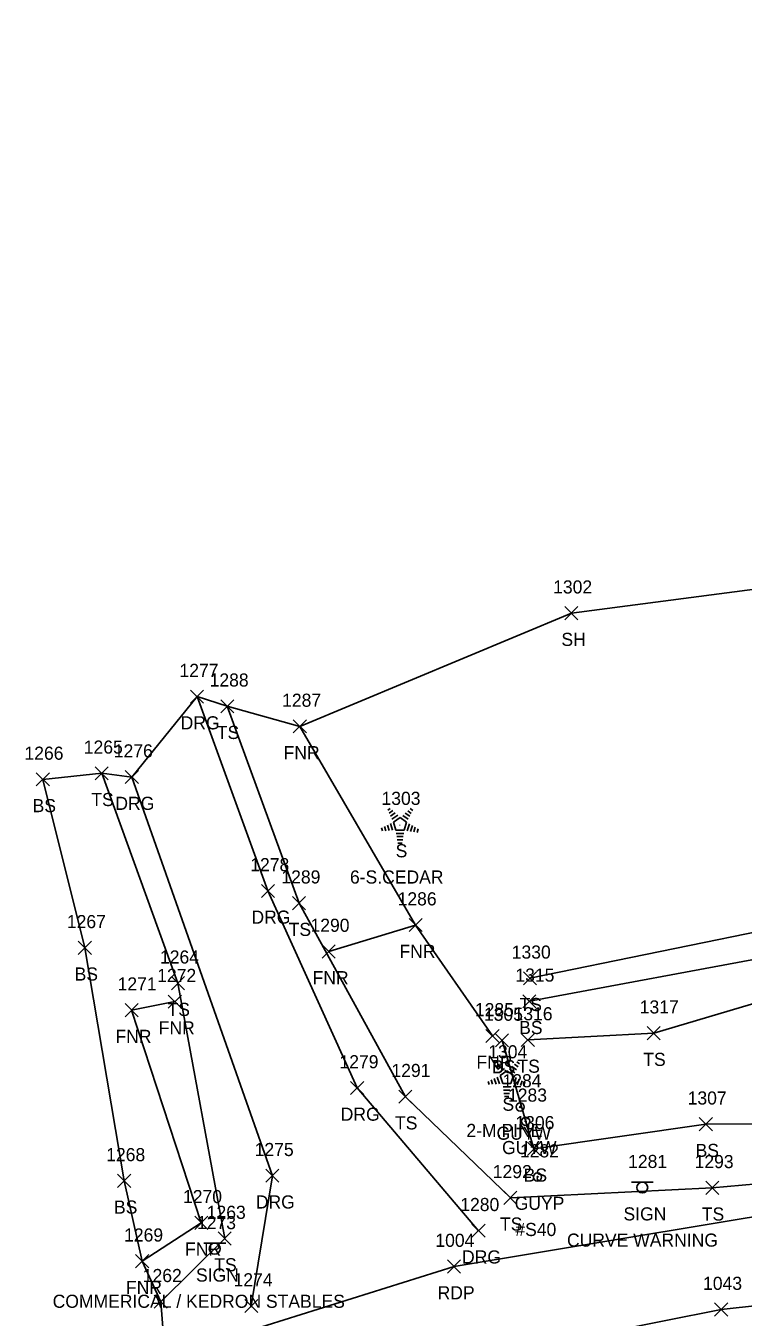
# Model space of a CAD drawing. Extents: x 1633660 to 1636532, y 388643 to 392631.
# Drawn here: x 1633659.9 to 1633769.3, y 388760.6 to 388957.6 of the extents above; entities that cross this region are included whole.
import ezdxf

# ---------------------------------------------------------------- set-up
doc = ezdxf.new("R2010")
doc.units = 0
for name, color, linetype in [('L_A', 7, 'Continuous'), ('L_C', 7, 'Continuous'), ('L_I', 7, 'Continuous'), ('L_TIC', 7, 'Continuous'), ('LELB', 7, 'Continuous'), ('LFNC', 7, 'Continuous'), ('LSOGP', 7, 'Continuous'), ('LTC', 7, 'Continuous'), ('P_A', 7, 'Continuous'), ('P_I', 7, 'Continuous'), ('P_TIC', 7, 'Continuous'), ('PET', 7, 'Continuous'), ('PRC', 7, 'Continuous'), ('R_A', 7, 'Continuous'), ('R_I', 7, 'Continuous'), ('R_TIC', 7, 'Continuous'), ('RDG', 7, 'Continuous'), ('S_A', 7, 'Continuous'), ('S_C', 7, 'Continuous'), ('S_I', 7, 'Continuous'), ('SSGN', 7, 'Continuous'), ('U_A', 7, 'Continuous'), ('U_C', 7, 'Continuous'), ('U_I', 7, 'Continuous'), ('UPGW', 7, 'Continuous')]:
    doc.layers.add(name, color=color, linetype=linetype)

msp = doc.modelspace()

# ---------------------------------------------------------------- linework, layer by layer
at = {"layer": 'L_TIC'}
for points in [[(1633742.09, 388866.97), (1633744.09, 388868.97)], [(1633744.09, 388866.97), (1633742.09, 388868.97)], [(1633689.59, 388852.77), (1633691.59, 388854.77)], [(1633691.59, 388852.77), (1633689.59, 388854.77)], [(1633700.66, 388849.69), (1633702.66, 388851.69)], [(1633702.66, 388849.69), (1633700.66, 388851.69)], [(1633661.45, 388841.61), (1633663.45, 388843.61)], [(1633663.45, 388841.61), (1633661.45, 388843.61)], [(1633670.44, 388842.54), (1633672.44, 388844.54)], [(1633672.44, 388842.54), (1633670.44, 388844.54)], [(1633700.55, 388822.73), (1633702.55, 388824.73)], [(1633702.55, 388822.73), (1633700.55, 388824.73)], [(1633718.32, 388819.39), (1633720.32, 388821.39)], [(1633720.32, 388819.39), (1633718.32, 388821.39)], [(1633667.86, 388815.92), (1633669.86, 388817.92)], [(1633669.86, 388815.92), (1633667.86, 388817.92)], [(1633705.07, 388815.36), (1633707.07, 388817.36)], [(1633707.07, 388815.36), (1633705.07, 388817.36)], [(1633735.77, 388811.27), (1633737.77, 388813.27)], [(1633737.77, 388811.27), (1633735.77, 388813.27)], [(1633682.07, 388810.52), (1633684.07, 388812.52)], [(1633684.07, 388810.52), (1633682.07, 388812.52)], [(1633681.59, 388807.71), (1633683.59, 388809.71)], [(1633683.59, 388807.71), (1633681.59, 388809.71)], [(1633735.68, 388807.76), (1633737.68, 388809.76)], [(1633737.68, 388807.76), (1633735.68, 388809.76)], [(1633674.99, 388806.41), (1633676.99, 388808.41)], [(1633676.99, 388806.41), (1633674.99, 388808.41)], [(1633730.06, 388802.48), (1633732.06, 388804.48)], [(1633732.06, 388802.48), (1633730.06, 388804.48)], [(1633731.52, 388801.79), (1633733.52, 388803.79)], [(1633733.52, 388801.79), (1633731.52, 388803.79)], [(1633735.45, 388801.86), (1633737.45, 388803.86)], [(1633737.45, 388801.86), (1633735.45, 388803.86)], [(1633754.65, 388802.9), (1633756.65, 388804.9)], [(1633756.65, 388802.9), (1633754.65, 388804.9)], [(1633716.77, 388793.21), (1633718.77, 388795.21)], [(1633718.77, 388793.21), (1633716.77, 388795.21)], [(1633762.6, 388789.01), (1633764.6, 388791.01)], [(1633764.6, 388789.01), (1633762.6, 388791.01)], [(1633736.38, 388785.25), (1633738.38, 388787.25)], [(1633738.38, 388785.25), (1633736.38, 388787.25)], [(1633673.86, 388780.37), (1633675.86, 388782.37)], [(1633675.86, 388780.37), (1633673.86, 388782.37)], [(1633732.79, 388777.78), (1633734.79, 388779.78)], [(1633734.79, 388777.78), (1633732.79, 388779.78)], [(1633763.59, 388779.31), (1633765.59, 388781.31)], [(1633765.59, 388779.31), (1633763.59, 388781.31)], [(1633685.62, 388773.97), (1633687.62, 388775.97)], [(1633687.62, 388773.97), (1633685.62, 388775.97)], [(1633689.2, 388771.57), (1633691.2, 388773.57)], [(1633691.2, 388771.57), (1633689.2, 388773.57)], [(1633676.6, 388768.11), (1633678.6, 388770.11)], [(1633678.6, 388768.11), (1633676.6, 388770.11)], [(1633679.44, 388761.93), (1633681.44, 388763.93)], [(1633681.44, 388761.93), (1633679.44, 388763.93)]]:
    msp.add_lwpolyline(points, dxfattribs=at)
at = {"layer": 'LELB'}
for points in [[(1633690.59, 388853.77), (1633701.55, 388823.73), (1633717.77, 388794.21), (1633733.79, 388778.78), (1633764.59, 388780.31), (1633801.16, 388783.54), (1633852.79, 388786.38)], [(1633680.44, 388762.93), (1633690.2, 388772.57), (1633683.07, 388811.52), (1633671.44, 388843.54)], [(1633662.45, 388842.61), (1633668.86, 388816.92), (1633674.86, 388781.37)], [(1633834.68, 388821.23), (1633803.62, 388822.68), (1633776.53, 388820.42), (1633736.77, 388812.27)], [(1633732.52, 388802.79), (1633737.38, 388786.25), (1633763.6, 388790.01), (1633804.22, 388790.21), (1633839.63, 388789.94), (1633849.49, 388790.37), (1633848.79, 388802.8), (1633836.81, 388813.44), (1633805.25, 388817.32), (1633774.99, 388815.91), (1633736.68, 388808.76)], [(1633736.45, 388802.86), (1633755.65, 388803.9), (1633782.21, 388811.79), (1633808.74, 388811.63), (1633837.08, 388809.23)]]:
    msp.add_lwpolyline(points, dxfattribs=at)
at = {"layer": 'LFNC'}
for points in [[(1633731.06, 388803.48), (1633719.32, 388820.39), (1633701.66, 388850.69)], [(1633706.07, 388816.36), (1633719.32, 388820.39)], [(1633677.6, 388769.11), (1633686.62, 388774.97), (1633675.99, 388807.41), (1633682.59, 388808.71)]]:
    msp.add_lwpolyline(points, dxfattribs=at)
at = {"layer": 'LSOGP'}
msp.add_lwpolyline([(1633910.94, 388898.06), (1633887.99, 388896.34), (1633879.79, 388892.06), (1633864.8, 388888.03), (1633862.62, 388887.47), (1633820.24, 388878.02), (1633775.34, 388872.21), (1633743.09, 388867.97), (1633701.66, 388850.69), (1633690.59, 388853.77), (1633685.99, 388855.24), (1633676.03, 388842.96), (1633671.44, 388843.54), (1633662.45, 388842.61), (1633668.86, 388816.92), (1633674.86, 388781.37), (1633677.6, 388769.11), (1633680.44, 388762.93), (1633681.12, 388754.49)], dxfattribs=at)
at = {"layer": 'LTC'}
for p, q in [((1633715.09, 388837.93), (1633715.45, 388838.19)), ((1633715.3, 388837.46), (1633715.83, 388837.85)), ((1633715.51, 388837), (1633716.21, 388837.51)), ((1633715.72, 388836.53), (1633716.6, 388837.17)), ((1633717.38, 388837.12), (1633718.19, 388836.54)), ((1633717.75, 388837.47), (1633718.43, 388836.98)), ((1633718.12, 388837.82), (1633718.67, 388837.42)), ((1633718.49, 388838.17), (1633718.91, 388837.87)), ((1633714.12, 388835.21), (1633714.28, 388834.74)), ((1633714.58, 388835.43), (1633714.79, 388834.77)), ((1633715.03, 388835.64), (1633715.31, 388834.81)), ((1633715.49, 388835.86), (1633715.82, 388834.84)), ((1633715.94, 388836.08), (1633716.96, 388836.81)), ((1633715.94, 388836.08), (1633716.33, 388834.88)), ((1633717.56, 388834.88), (1633716.33, 388834.88)), ((1633716.96, 388836.81), (1633717.95, 388836.09)), ((1633717.95, 388836.09), (1633717.56, 388834.88)), ((1633718.39, 388835.82), (1633718.05, 388834.78)), ((1633718.84, 388835.57), (1633718.55, 388834.68)), ((1633719.28, 388835.32), (1633719.04, 388834.59)), ((1633719.72, 388835.07), (1633719.54, 388834.49)), ((1633717.52, 388834.38), (1633716.38, 388834.38)), ((1633717.44, 388833.88), (1633716.45, 388833.88)), ((1633717.36, 388833.38), (1633716.52, 388833.38)), ((1633717.27, 388832.88), (1633716.6, 388832.88)), ((1633731.38, 388799.27), (1633731.73, 388799.52)), ((1633734.77, 388799.51), (1633735.19, 388799.2)), ((1633731.59, 388798.8), (1633732.11, 388799.19)), ((1633731.8, 388798.34), (1633732.5, 388798.85)), ((1633732, 388797.87), (1633732.88, 388798.51)), ((1633732.23, 388797.42), (1633733.24, 388798.15)), ((1633733.24, 388798.15), (1633734.24, 388797.42)), ((1633733.66, 388798.46), (1633734.47, 388797.87)), ((1633734.24, 388797.42), (1633733.85, 388796.22)), ((1633734.03, 388798.81), (1633734.71, 388798.32)), ((1633734.4, 388799.16), (1633734.95, 388798.76)), ((1633730.41, 388796.55), (1633730.56, 388796.08)), ((1633730.86, 388796.76), (1633731.08, 388796.11)), ((1633731.32, 388796.98), (1633731.59, 388796.14)), ((1633731.77, 388797.2), (1633732.11, 388796.18)), ((1633732.23, 388797.42), (1633732.62, 388796.22)), ((1633733.85, 388796.22), (1633732.62, 388796.22)), ((1633733.81, 388795.72), (1633732.66, 388795.72)), ((1633734.68, 388797.15), (1633734.34, 388796.11)), ((1633735.12, 388796.9), (1633734.83, 388796.02)), ((1633735.56, 388796.65), (1633735.33, 388795.92)), ((1633736.01, 388796.4), (1633735.82, 388795.83)), ((1633733.72, 388795.22), (1633732.74, 388795.22)), ((1633733.64, 388794.72), (1633732.81, 388794.72)), ((1633733.56, 388794.22), (1633732.88, 388794.22))]:
    msp.add_line(p, q, dxfattribs=at)
at = {"layer": 'P_TIC'}
for points in [[(1633724.19, 388767.3), (1633726.19, 388769.3)], [(1633726.19, 388767.3), (1633724.19, 388769.3)], [(1633764.95, 388760.74), (1633766.95, 388762.74)], [(1633766.95, 388760.74), (1633764.95, 388762.74)]]:
    msp.add_lwpolyline(points, dxfattribs=at)
at = {"layer": 'PET'}
msp.add_lwpolyline([(1633681.12, 388754.49), (1633725.19, 388768.3), (1633776.36, 388776.79), (1633828.74, 388780.84), (1633883.05, 388781.87), (1633940.05, 388783.92), (1633980.78, 388788.35), (1634030.66, 388797.38), (1634082.16, 388811.29), (1634131.93, 388828.18), (1634182.59, 388846.73), (1634235.61, 388867.86)], dxfattribs=at)
at = {"layer": 'PRC'}
msp.add_lwpolyline([(1633685.21, 388740.89), (1633722.47, 388753.09), (1633765.95, 388761.74), (1633808.84, 388766.45), (1633860.63, 388768.05), (1633911.93, 388769.08), (1633965.45, 388772.58), (1634019.68, 388781.06), (1634071.37, 388793.87), (1634111.14, 388806.36), (1634160.92, 388824.06), (1634207.93, 388842.02), (1634253.71, 388860.36), (1634302.74, 388880.25), (1634347.86, 388899.14), (1634390.05, 388916.89), (1634425.6, 388933.8), (1634443.27, 388943.77), (1634464.46, 388957.57)], dxfattribs=at)
at = {"layer": 'R_TIC'}
for points in [[(1633684.99, 388854.24), (1633686.99, 388856.24)], [(1633686.99, 388854.24), (1633684.99, 388856.24)], [(1633675.03, 388841.96), (1633677.03, 388843.96)], [(1633677.03, 388841.96), (1633675.03, 388843.96)], [(1633695.79, 388824.6), (1633697.79, 388826.6)], [(1633697.79, 388824.6), (1633695.79, 388826.6)], [(1633709.41, 388794.54), (1633711.41, 388796.54)], [(1633711.41, 388794.54), (1633709.41, 388796.54)], [(1633696.47, 388781.15), (1633698.47, 388783.15)], [(1633698.47, 388781.15), (1633696.47, 388783.15)], [(1633727.92, 388772.76), (1633729.92, 388774.76)], [(1633729.92, 388772.76), (1633727.92, 388774.76)], [(1633693.25, 388761.28), (1633695.25, 388763.28)], [(1633695.25, 388761.28), (1633693.25, 388763.28)]]:
    msp.add_lwpolyline(points, dxfattribs=at)
at = {"layer": 'RDG'}
for points in [[(1633685.99, 388855.24), (1633696.79, 388825.6), (1633710.41, 388795.54), (1633728.92, 388773.76)], [(1633694.25, 388762.28), (1633697.47, 388782.15), (1633676.03, 388842.96)]]:
    msp.add_lwpolyline(points, dxfattribs=at)
at = {"layer": 'SSGN'}
for p, q in [((1633752.25, 388781.18), (1633755.59, 388781.18)), ((1633753.9, 388780.35), (1633753.9, 388780.35)), ((1633687.03, 388771.85), (1633690.37, 388771.85)), ((1633688.68, 388771.02), (1633688.68, 388771.02))]:
    msp.add_line(p, q, dxfattribs=at)
for centre in [(1633753.9, 388780.35), (1633688.68, 388771.02)]:
    msp.add_circle(centre, 0.833, dxfattribs=at)
at = {"layer": 'UPGW'}
for centre, radius in [((1633735.28, 388792.64), 0.625), ((1633735.28, 388792.64), 0.0833), ((1633736.11, 388790.45), 0.625), ((1633736.11, 388790.45), 0.0833), ((1633737.93, 388781.95), 0.625), ((1633737.93, 388781.95), 0.0833)]:
    msp.add_circle(centre, radius, dxfattribs=at)

# ---------------------------------------------------------------- texts
at = {"layer": 'L_A'}
for s, p in [('SH', (1633741.57, 388862.97)), ('TS', (1633689, 388848.77)), ('FNR', (1633699.19, 388845.69)), ('BS', (1633660.89, 388837.61)), ('TS', (1633669.85, 388838.54)), ('S', (1633716.28, 388830.72)), ('TS', (1633699.96, 388818.73)), ('FNR', (1633716.86, 388815.39)), ('BS', (1633667.3, 388811.92)), ('FNR', (1633703.61, 388811.36)), ('TS', (1633735.18, 388807.27)), ('TS', (1633681.48, 388806.52)), ('FNR', (1633680.13, 388803.71)), ('BS', (1633735.12, 388803.76)), ('FNR', (1633673.53, 388802.41)), ('FNR', (1633728.6, 388798.48)), ('BS', (1633730.96, 388797.79)), ('TS', (1633734.86, 388797.86)), ('TS', (1633754.06, 388798.9)), ('S', (1633732.57, 388792.06)), ('TS', (1633716.18, 388789.21)), ('BS', (1633762.04, 388785.01)), ('BS', (1633735.82, 388781.25)), ('BS', (1633673.31, 388776.37)), ('TS', (1633732.2, 388773.78)), ('TS', (1633762.99, 388775.31)), ('FNR', (1633684.15, 388769.97)), ('TS', (1633688.61, 388767.57)), ('FNR', (1633675.14, 388764.11))]:
    msp.add_text(s, height=2, dxfattribs=at).set_placement(p)
at = {"layer": 'L_C'}
for s, p in [('6-S.CEDAR', (1633709.31, 388826.72)), ('2-M.PINE', (1633727.07, 388788.06))]:
    msp.add_text(s, height=2, dxfattribs=at).set_placement(p)
at = {"layer": 'L_I'}
for s, p in [('1302', (1633740.31, 388870.97)), ('1288', (1633687.9, 388856.77)), ('1287', (1633698.96, 388853.69)), ('1266', (1633659.65, 388845.61)), ('1265', (1633668.7, 388846.54)), ('1303', (1633714.12, 388838.72)), ('1289', (1633698.85, 388826.73)), ('1286', (1633716.58, 388823.39)), ('1267', (1633666.12, 388819.92)), ('1290', (1633703.29, 388819.36)), ('1330', (1633733.99, 388815.27)), ('1264', (1633680.33, 388814.52)), ('1272', (1633679.9, 388811.71)), ('1315', (1633734.55, 388811.76)), ('1271', (1633673.86, 388810.41)), ('1285', (1633728.37, 388806.48)), ('1305', (1633729.75, 388805.79)), ('1316', (1633734.27, 388805.86)), ('1317', (1633753.52, 388806.9)), ('1304', (1633730.41, 388800.06)), ('1291', (1633715.64, 388797.21)), ('1307', (1633760.83, 388793.01)), ('1306', (1633734.55, 388789.25)), ('1268', (1633672.12, 388784.37)), ('1292', (1633731.1, 388781.78)), ('1293', (1633761.89, 388783.31)), ('1270', (1633683.84, 388777.97)), ('1263', (1633687.46, 388775.57)), ('1269', (1633674.85, 388772.11)), ('1262', (1633677.7, 388765.93))]:
    msp.add_text(s, height=2, dxfattribs=at).set_placement(p)
at = {"layer": 'LTC'}
for p in [(1633716.84, 388835.83), (1633733.12, 388797.16)]:
    msp.add_text('.', height=1.04, rotation=270, dxfattribs=at).set_placement(p)
at = {"layer": 'P_A'}
msp.add_text('RDP', height=2, dxfattribs=at).set_placement((1633722.68, 388763.3))
at = {"layer": 'P_I'}
for s, p in [('1004', (1633722.34, 388771.3)), ('1043', (1633763.18, 388764.74))]:
    msp.add_text(s, height=2, dxfattribs=at).set_placement(p)
at = {"layer": 'R_A'}
for p in [(1633683.48, 388850.24), (1633673.52, 388837.96), (1633694.28, 388820.6), (1633707.9, 388790.54), (1633694.95, 388777.15), (1633726.41, 388768.76)]:
    msp.add_text('DRG', height=2, dxfattribs=at).set_placement(p)
at = {"layer": 'R_I'}
for s, p in [('1277', (1633683.3, 388858.24)), ('1276', (1633673.28, 388845.96)), ('1278', (1633694.1, 388828.6)), ('1279', (1633707.71, 388798.54)), ('1275', (1633694.77, 388785.15)), ('1280', (1633726.14, 388776.76)), ('1274', (1633691.55, 388765.28))]:
    msp.add_text(s, height=2, dxfattribs=at).set_placement(p)
at = {"layer": 'S_A'}
for p in [(1633751.04, 388775.33), (1633685.82, 388766)]:
    msp.add_text('SIGN', height=2, dxfattribs=at).set_placement(p)
at = {"layer": 'S_C'}
for s, p in [('CURVE WARNING', (1633742.42, 388771.33)), ('COMMERICAL / KEDRON STABLES', (1633663.95, 388762))]:
    msp.add_text(s, height=2, dxfattribs=at).set_placement(p)
at = {"layer": 'S_I'}
for s, p in [('1281', (1633751.75, 388783.33)), ('1273', (1633685.97, 388774))]:
    msp.add_text(s, height=2, dxfattribs=at).set_placement(p)
at = {"layer": 'U_A'}
for s, p in [('GUYW', (1633731.67, 388787.64)), ('GUYW', (1633732.51, 388785.45)), ('GUYP', (1633734.44, 388776.95))]:
    msp.add_text(s, height=2, dxfattribs=at).set_placement(p)
at = {"layer": 'U_C'}
msp.add_text('#S40', height=2, dxfattribs=at).set_placement((1633734.54, 388772.95))
at = {"layer": 'U_I'}
for s, p in [('1284', (1633732.58, 388795.64)), ('1283', (1633733.42, 388793.45)), ('1282', (1633735.24, 388784.95))]:
    msp.add_text(s, height=2, dxfattribs=at).set_placement(p)

doc.saveas('drawing.dxf')
